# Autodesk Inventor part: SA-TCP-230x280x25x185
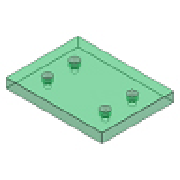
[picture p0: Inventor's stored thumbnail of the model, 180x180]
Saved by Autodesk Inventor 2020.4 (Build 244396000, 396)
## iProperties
Created: 2019-01
Part Number: SA-TCP-230x280x25x185
Material: S 55 C
Description: Top Clamping Plate
Document SubType Name: Modeling
Designer: mel
Standard Revision: 1
Manufacturer: FUTABA
Language: fr-FR
Size Designation: 230x280x25x185
Categories: <MemberInstance><Categories><Category DisplayName="Moule" InternalName="349578f2-f4d4-4954-8c09-8e99297a61c0" Mnemonic="MOLD"><Category DisplayName="Plaque de m
Density: 7.85 g/cm^3
Appearance: Clear - Green 1
IsCustomPart: 1
Author: mel
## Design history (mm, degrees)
sketch "Sketch1"
  geometry: L1 (-140, 115)-(140, 115); L2 (140, 115)-(140, -115); L3 (140, -115)-(-140, -115); L4 (-140, -115)-(-140, 115); 3 further points
  constraints: 8 end point, 2 midpoint, 2 parallel, 1 horizontal, 1 horizontal alignment, 1 perpendicular, 1 vertical alignment
  dimensions: "d72" = 280 distance between parallel lines of L2 L4 (= W_); "d73" = 230 distance between parallel lines of L3 L1 (= L)
extrude "Extrusion1" new body sketch "Sketch1" distance "d20" = 25 (= H_); taper "d30" = 0 deg
sketch "Sketch2"
  geometry: 2 further points
  dimensions: "d53" = 92.5 horizontal distance of point (0, 0) point (-92.5, 53) (= 0.5 x S1_W); "d54" = 53 vertical distance of point (0, 0) point (-92.5, 53) (= 0.5 x S1_L)
hole "Hole1" sketch "Sketch2" at (-92.5, 53) diameter "d55" = 14 (= S1_d1); stored, may be unused: countersink angle "d59" = 90 deg, drill point angle "d61" = 0 deg; dims "d56" = 6, "d57" = 20 (= S1_d2), "d58" = 13 (= S1_k), "d60" = 25 (= H_)
pattern_linear "Rectangular Pattern1" dims "d64" = 106 (computed from S1_L, Ns), "d67" = 185 (computed from S1_W, Nw)
chamfer "Chamfer1" distance "d68" = 0.5; stored, may be unused: second distance "d69" = 2, angle "d71" = 45 deg
feature "Sculpter1"
feature "Sculpter2"
body "Solid1"
feature "Surface1"
body "Srf1"
feature "Surface2"
body "Srf2"
other parameters: "L" = 230 [user parameter; used in 1 equation term], "W_" = 280 [user parameter; used in 1 equation term], "H_" = 25 [user parameter; used in 2 equation terms], "S1_W" = 185 [user parameter; used in 2 equation terms], "S1_d1" = 14 [user parameter; used in 1 equation term], "S1_d2" = 20 [user parameter; used in 1 equation term], "S1_k" = 13 [user parameter; used in 1 equation term], "S1_L" = 106 [user parameter; used in 2 equation terms]
